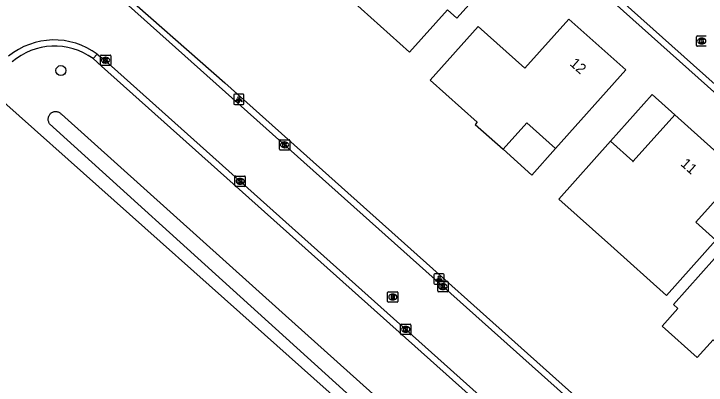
# Model space of a CAD drawing. Extents: x 157663 to 158496, y 379212 to 380934.
# Drawn here: x 158375.9 to 158443, y 380243 to 380278.9 of the extents above; entities that cross this region are included whole.
import ezdxf

# ---------------------------------------------------------------- set-up
doc = ezdxf.new("R2010")
doc.units = 0
for name, color, linetype in [('IMGEO_Boom', 7, 'Continuous'), ('IMGEO_Groenvoorziening', 7, 'Continuous'), ('IMGEO_Kolk', 7, 'Continuous'), ('IMGEO_Lichtpunt', 7, 'Continuous'), ('IMGEO_Pand', 7, 'Continuous'), ('IMGEO_Pand_nummerreeks', 7, 'Continuous'), ('IMGEO_Pand_overbouw', 7, 'Continuous'), ('IMGEO_Rijbaan_lokaal_open', 7, 'Continuous'), ('IMGEO_Rioolput', 7, 'Continuous'), ('IMGEO_Voetpad_open', 7, 'Continuous'), ('IMGEO_Waterloop', 7, 'Continuous')]:
    doc.layers.add(name, color=color, linetype=linetype)

msp = doc.modelspace()

# ---------------------------------------------------------------- linework, layer by layer
at = {"layer": 'IMGEO_Boom'}
msp.add_circle((158380.446, 380273.438), 0.489, dxfattribs=at)
at = {"layer": 'IMGEO_Groenvoorziening'}
msp.add_lwpolyline([(158436.002, 380187.68), (158429.436, 380221.799), (158397.765, 380250), (158373.398, 380271.696)], dxfattribs=at)
at = {"layer": 'IMGEO_Kolk'}
for p, q in [((158442.029, 380275.869), (158442.029, 380276.721)), ((158442.104, 380276.795), (158442.956, 380276.795)), ((158442.517, 380276.575), (158442.542, 380276.575)), ((158442.956, 380275.795), (158442.104, 380275.795)), ((158442.54, 380276.015), (158442.515, 380276.015)), ((158384.35, 380274.944), (158385.202, 380274.944)), ((158384.275, 380274.018), (158384.275, 380274.87)), ((158384.763, 380274.724), (158384.788, 380274.724)), ((158385.276, 380274.87), (158385.276, 380274.018)), ((158385.202, 380273.944), (158384.35, 380273.944)), ((158384.786, 380274.164), (158384.761, 380274.164)), ((158401.618, 380265.819), (158401.618, 380266.671)), ((158401.693, 380266.745), (158402.545, 380266.745)), ((158402.106, 380266.525), (158402.131, 380266.525)), ((158402.619, 380266.671), (158402.619, 380265.819)), ((158402.545, 380265.745), (158401.693, 380265.745)), ((158402.129, 380265.965), (158402.104, 380265.965)), ((158397.307, 380262.295), (158397.307, 380263.147)), ((158397.382, 380263.221), (158398.234, 380263.221)), ((158397.795, 380263.001), (158397.82, 380263.001)), ((158398.308, 380263.147), (158398.308, 380262.295)), ((158398.234, 380262.221), (158397.382, 380262.221)), ((158397.818, 380262.441), (158397.793, 380262.441)), ((158416.95, 380252.091), (158416.95, 380252.943)), ((158417.025, 380253.017), (158417.877, 380253.017)), ((158417.951, 380252.943), (158417.951, 380252.091)), ((158417.461, 380252.237), (158417.436, 380252.237)), ((158417.438, 380252.797), (158417.463, 380252.797)), ((158417.877, 380252.017), (158417.025, 380252.017)), ((158413.351, 380247.943), (158413.351, 380248.795)), ((158413.426, 380248.869), (158414.278, 380248.869)), ((158414.352, 380248.795), (158414.352, 380247.943)), ((158413.839, 380248.649), (158413.864, 380248.649)), ((158414.278, 380247.869), (158413.426, 380247.869)), ((158413.862, 380248.089), (158413.837, 380248.089))]:
    msp.add_line(p, q, dxfattribs=at)
for points in [[(158442.029, 380275.869), (158442.029, 380276.721)], [(158442.104, 380276.795), (158442.956, 380276.795)], [(158442.35, 380276.495), (158442.473, 380276.495), (158442.473, 380276.344), (158442.603, 380276.495), (158442.767, 380276.495), (158442.621, 380276.344), (158442.774, 380276.095), (158442.622, 380276.095), (158442.537, 380276.259), (158442.473, 380276.192), (158442.473, 380276.095), (158442.35, 380276.095), (158442.35, 380276.495)], [(158442.956, 380275.795), (158442.104, 380275.795)], [(158384.35, 380274.944), (158385.202, 380274.944)], [(158384.275, 380274.018), (158384.275, 380274.87)], [(158384.596, 380274.644), (158384.719, 380274.644), (158384.719, 380274.493), (158384.849, 380274.644), (158385.013, 380274.644), (158384.867, 380274.493), (158385.02, 380274.244), (158384.868, 380274.244), (158384.783, 380274.408), (158384.719, 380274.341), (158384.719, 380274.244), (158384.596, 380274.244), (158384.596, 380274.644)], [(158385.276, 380274.87), (158385.276, 380274.018)], [(158385.202, 380273.944), (158384.35, 380273.944)], [(158401.618, 380265.819), (158401.618, 380266.671)], [(158401.693, 380266.745), (158402.545, 380266.745)], [(158401.939, 380266.445), (158402.062, 380266.445), (158402.062, 380266.294), (158402.192, 380266.445), (158402.356, 380266.445), (158402.21, 380266.294), (158402.363, 380266.045), (158402.211, 380266.045), (158402.126, 380266.209), (158402.062, 380266.142), (158402.062, 380266.045), (158401.939, 380266.045), (158401.939, 380266.445)], [(158402.619, 380266.671), (158402.619, 380265.819)], [(158402.545, 380265.745), (158401.693, 380265.745)], [(158397.307, 380262.295), (158397.307, 380263.147)], [(158397.382, 380263.221), (158398.234, 380263.221)], [(158397.628, 380262.921), (158397.751, 380262.921), (158397.751, 380262.77), (158397.881, 380262.921), (158398.045, 380262.921), (158397.899, 380262.77), (158398.052, 380262.521), (158397.9, 380262.521), (158397.815, 380262.685), (158397.751, 380262.618), (158397.751, 380262.521), (158397.628, 380262.521), (158397.628, 380262.921)], [(158398.308, 380263.147), (158398.308, 380262.295)], [(158398.234, 380262.221), (158397.382, 380262.221)], [(158416.95, 380252.091), (158416.95, 380252.943)], [(158417.025, 380253.017), (158417.877, 380253.017)], [(158417.951, 380252.943), (158417.951, 380252.091)], [(158417.271, 380252.717), (158417.394, 380252.717), (158417.394, 380252.566), (158417.524, 380252.717), (158417.688, 380252.717), (158417.542, 380252.566), (158417.695, 380252.317), (158417.543, 380252.317), (158417.458, 380252.481), (158417.394, 380252.414), (158417.394, 380252.317), (158417.271, 380252.317), (158417.271, 380252.717)], [(158417.877, 380252.017), (158417.025, 380252.017)], [(158413.351, 380247.943), (158413.351, 380248.795)], [(158413.426, 380248.869), (158414.278, 380248.869)], [(158414.352, 380248.795), (158414.352, 380247.943)], [(158413.672, 380248.569), (158413.795, 380248.569), (158413.795, 380248.418), (158413.925, 380248.569), (158414.089, 380248.569), (158413.943, 380248.418), (158414.096, 380248.169), (158413.944, 380248.169), (158413.859, 380248.333), (158413.795, 380248.266), (158413.795, 380248.169), (158413.672, 380248.169), (158413.672, 380248.569)], [(158414.278, 380247.869), (158413.426, 380247.869)]]:
    msp.add_lwpolyline(points, dxfattribs=at)
for centre, start, end in [((158442.106, 380276.719), 91.55205, 178.44795), ((158442.106, 380276.719), 91.55205, 178.44795), ((158442.106, 380275.871), 181.55205, 268.44795), ((158442.106, 380275.871), 181.55205, 268.44795), ((158384.352, 380274.868), 91.55205, 178.44795), ((158384.352, 380274.868), 91.55205, 178.44795), ((158385.2, 380274.868), 1.55205, 88.44795), ((158385.2, 380274.868), 1.55205, 88.44795), ((158384.352, 380274.02), 181.55205, 268.44795), ((158384.352, 380274.02), 181.55205, 268.44795), ((158385.2, 380274.02), 271.55205, 358.44795), ((158385.2, 380274.02), 271.55205, 358.44795), ((158401.695, 380266.669), 91.55205, 178.44795), ((158401.695, 380266.669), 91.55205, 178.44795), ((158402.543, 380266.669), 1.55205, 88.44795), ((158402.543, 380266.669), 1.55205, 88.44795), ((158401.695, 380265.821), 181.55205, 268.44795), ((158401.695, 380265.821), 181.55205, 268.44795), ((158402.543, 380265.821), 271.55205, 358.44795), ((158402.543, 380265.821), 271.55205, 358.44795), ((158397.384, 380263.145), 91.55205, 178.44795), ((158397.384, 380263.145), 91.55205, 178.44795), ((158398.232, 380263.145), 1.55205, 88.44795), ((158398.232, 380263.145), 1.55205, 88.44795), ((158397.384, 380262.297), 181.55205, 268.44795), ((158397.384, 380262.297), 181.55205, 268.44795), ((158398.232, 380262.297), 271.55205, 358.44795), ((158398.232, 380262.297), 271.55205, 358.44795), ((158417.027, 380252.941), 91.55205, 178.44795), ((158417.027, 380252.941), 91.55205, 178.44795), ((158417.875, 380252.941), 1.55205, 88.44795), ((158417.875, 380252.941), 1.55205, 88.44795), ((158417.027, 380252.093), 181.55205, 268.44795), ((158417.027, 380252.093), 181.55205, 268.44795), ((158417.875, 380252.093), 271.55205, 358.44795), ((158417.875, 380252.093), 271.55205, 358.44795), ((158413.428, 380248.793), 91.55205, 178.44795), ((158413.428, 380248.793), 91.55205, 178.44795), ((158414.276, 380248.793), 1.55205, 88.44795), ((158414.276, 380248.793), 1.55205, 88.44795), ((158413.428, 380247.945), 181.55205, 268.44795), ((158413.428, 380247.945), 181.55205, 268.44795), ((158414.276, 380247.945), 271.55205, 358.44795), ((158414.276, 380247.945), 271.55205, 358.44795)]:
    msp.add_arc(centre, 0.0765, start, end, dxfattribs=at)
for centre, major_axis, ratio, start_param, end_param in [((158442.516, 380276.295), (-0.387, 0.002), 0.722429, 4.712389, 7.853982), ((158442.541, 380276.295), (-0.39, 0.002), 0.717154, 1.570796, 4.712389), ((158384.762, 380274.444), (-0.387, 0.002), 0.722429, 4.712389, 7.853982), ((158384.787, 380274.444), (-0.39, 0.002), 0.717154, 1.570796, 4.712389), ((158402.105, 380266.245), (-0.387, 0.002), 0.722429, 4.712389, 7.853982), ((158402.13, 380266.245), (-0.39, 0.002), 0.717154, 1.570796, 4.712389), ((158397.794, 380262.721), (-0.387, 0.002), 0.722429, 4.712389, 7.853982), ((158397.819, 380262.721), (-0.39, 0.002), 0.717154, 1.570796, 4.712389), ((158417.437, 380252.517), (-0.387, 0.002), 0.722429, 4.712389, 7.853982), ((158417.462, 380252.517), (-0.39, 0.002), 0.717154, 1.570796, 4.712389), ((158413.838, 380248.369), (-0.387, 0.002), 0.722429, 4.712389, 7.853982), ((158413.863, 380248.369), (-0.39, 0.002), 0.717154, 1.570796, 4.712389)]:
    msp.add_ellipse(centre, major_axis=major_axis, ratio=ratio, start_param=start_param, end_param=end_param, dxfattribs=at)
at = {"layer": 'IMGEO_Lichtpunt'}
for p, q in [((158397.184, 380271.042), (158397.184, 380270.235)), ((158397.184, 380271.042), (158397.184, 380270.235)), ((158398.086, 380271.137), (158397.278, 380271.137)), ((158398.086, 380271.137), (158397.278, 380271.137)), ((158398.18, 380270.235), (158398.18, 380271.042)), ((158398.18, 380270.235), (158398.18, 380271.042)), ((158397.278, 380270.141), (158398.086, 380270.141)), ((158397.278, 380270.141), (158398.086, 380270.141)), ((158416.588, 380253.647), (158416.588, 380252.84)), ((158416.588, 380253.647), (158416.588, 380252.84)), ((158417.49, 380253.742), (158416.682, 380253.742)), ((158417.49, 380253.742), (158416.682, 380253.742)), ((158417.584, 380252.84), (158417.584, 380253.647)), ((158417.584, 380252.84), (158417.584, 380253.647)), ((158416.682, 380252.746), (158417.49, 380252.746)), ((158416.682, 380252.746), (158417.49, 380252.746))]:
    msp.add_line(p, q, dxfattribs=at)
for points in [[(158397.558, 380270.706), (158397.597, 380270.678), (158397.409, 380270.416), (158397.371, 380270.443), (158397.558, 380270.706)], [(158397.66, 380270.658), (158397.707, 380270.658), (158397.707, 380270.336), (158397.66, 380270.336), (158397.66, 380270.658)], [(158397.77, 380270.678), (158397.808, 380270.705), (158397.995, 380270.443), (158397.956, 380270.415), (158397.77, 380270.678)], [(158416.962, 380253.311), (158417.001, 380253.283), (158416.813, 380253.021), (158416.775, 380253.048), (158416.962, 380253.311)], [(158417.064, 380253.263), (158417.111, 380253.263), (158417.111, 380252.941), (158417.064, 380252.941), (158417.064, 380253.263)], [(158417.174, 380253.283), (158417.212, 380253.31), (158417.399, 380253.048), (158417.36, 380253.02), (158417.174, 380253.283)]]:
    msp.add_lwpolyline(points, dxfattribs=at)
for centre in [(158397.683, 380270.84), (158417.087, 380253.445)]:
    msp.add_circle(centre, 0.0994, dxfattribs=at)
for centre, start, end in [((158397.278, 380271.042), 90, 180), ((158397.278, 380271.042), 90, 180), ((158398.086, 380271.042), 0, 90), ((158398.086, 380271.042), 0, 90), ((158397.278, 380270.235), 180, 270), ((158397.278, 380270.235), 180, 270), ((158398.086, 380270.235), 270, 0), ((158398.086, 380270.235), 270, 360), ((158416.682, 380253.647), 90, 180), ((158416.682, 380253.647), 90, 180), ((158417.49, 380253.647), 0, 90), ((158417.49, 380253.647), 0, 90), ((158416.682, 380252.84), 180, 270), ((158416.682, 380252.84), 180, 270), ((158417.49, 380252.84), 270, 0), ((158417.49, 380252.84), 270, 360)]:
    msp.add_arc(centre, 0.0946, start, end, dxfattribs=at)
at = {"layer": 'IMGEO_Pand'}
for points in [[(158422.031, 380282.141), (158418.975, 380284.874), (158419.836, 380285.836), (158412.917, 380292.022), (158408.761, 380287.374), (158410.312, 380285.987), (158406.707, 380281.954), (158414.228, 380275.23), (158417.897, 380279.333), (158418.799, 380278.526), (158422.031, 380282.141)], [(158435.167, 380273.507), (158429.659, 380278.431), (158425.402, 380273.668), (158420.872, 380277.718), (158416.219, 380272.513), (158420.786, 380268.431), (158420.591, 380268.213), (158423.278, 380265.812), (158425.568, 380268.374), (158425.57, 380268.376), (158425.573, 380268.377), (158425.576, 380268.377), (158425.579, 380268.376), (158425.582, 380268.374), (158428.359, 380265.892), (158435.167, 380273.507)], [(158439.909, 380269.158), (158435.877, 380264.648), (158435.874, 380264.646), (158435.871, 380264.645), (158435.867, 380264.646), (158435.863, 380264.648), (158433.686, 380266.594), (158428.685, 380260.999), (158433.714, 380256.503), (158439.126, 380251.665), (158443.899, 380257.009), (158441.96, 380258.741), (158446.225, 380263.512), (158439.909, 380269.158)], [(158450.556, 380258.336), (158447.331, 380254.728), (158445.082, 380256.738), (158439.782, 380250.791), (158440.224, 380250.396), (158438.683, 380248.673), (158442.08, 380245.635), (158443.62, 380247.358), (158444.259, 380246.787), (158448.438, 380243.05), (158453.561, 380248.779), (158454.653, 380250), (158456.98, 380252.603), (158455.593, 380253.843), (158455.942, 380254.234), (158455.099, 380254.988), (158454.745, 380254.591), (158450.556, 380258.336)]]:
    msp.add_lwpolyline(points, dxfattribs=at)
at = {"layer": 'IMGEO_Pand_overbouw'}
for points in [[(158439.909, 380269.158), (158437.725, 380271.111), (158433.686, 380266.594), (158435.863, 380264.648), (158435.867, 380264.646), (158435.871, 380264.645), (158435.874, 380264.646), (158435.877, 380264.648)], [(158423.278, 380265.812), (158426.062, 380263.323), (158428.359, 380265.892), (158425.582, 380268.374), (158425.579, 380268.376), (158425.576, 380268.377), (158425.573, 380268.377), (158425.57, 380268.376), (158425.568, 380268.374)]]:
    msp.add_lwpolyline(points, close=True, dxfattribs=at)
at = {"layer": 'IMGEO_Rijbaan_lokaal_open'}
for points in [[(158455.226, 380261.928), (158407.817, 380304.245)], [(158444.879, 380228.012), (158386.082, 380280.588)], [(158383.955, 380275.03), (158384.74, 380274.414), (158451.982, 380214.262)]]:
    msp.add_lwpolyline(points, dxfattribs=at)
msp.add_arc((158379.792, 380269.395), 7.006, 53.5431, 129.22981, dxfattribs=at)
at = {"layer": 'IMGEO_Rioolput'}
for p, q in [((158412.097, 380251.077), (158412.097, 380251.929)), ((158412.172, 380252.003), (158413.024, 380252.003)), ((158412.585, 380251.783), (158412.61, 380251.783)), ((158413.098, 380251.929), (158413.098, 380251.077)), ((158413.024, 380251.003), (158412.172, 380251.003)), ((158412.608, 380251.223), (158412.583, 380251.223))]:
    msp.add_line(p, q, dxfattribs=at)
for points in [[(158412.097, 380251.077), (158412.097, 380251.929)], [(158412.172, 380252.003), (158413.024, 380252.003)], [(158412.686, 380251.701), (158412.434, 380251.703), (158412.434, 380251.303)], [(158412.612, 380251.622), (158412.558, 380251.622), (158412.558, 380251.541)], [(158412.558, 380251.541), (158412.61, 380251.541)], [(158413.098, 380251.929), (158413.098, 380251.077)], [(158413.024, 380251.003), (158412.172, 380251.003)], [(158412.434, 380251.303), (158412.558, 380251.303), (158412.558, 380251.465), (158412.569, 380251.465)], [(158412.616, 380251.436), (158412.687, 380251.303), (158412.827, 380251.303), (158412.762, 380251.429)]]:
    msp.add_lwpolyline(points, dxfattribs=at)
for centre, radius, start, end in [((158412.174, 380251.927), 0.0765, 91.55205, 178.44795), ((158412.174, 380251.927), 0.0765, 91.55205, 178.44795), ((158412.594, 380251.73), 0.19, 274.7715, 282.96867), ((158412.618, 380251.526), 0.0964, 77.00612, 93.18647), ((158412.632, 380251.583), 0.0378, 276.66336, 79.67722), ((158412.685, 380251.591), 0.109, 350.36119, 89.41601), ((158412.683, 380251.591), 0.112, 277.58423, 350.98172), ((158412.667, 380251.376), 0.108, 29.51342, 73.79051), ((158413.022, 380251.927), 0.0765, 1.55205, 88.44795), ((158413.022, 380251.927), 0.0765, 1.55205, 88.44795), ((158412.174, 380251.079), 0.0765, 181.55205, 268.44795), ((158412.174, 380251.079), 0.0765, 181.55205, 268.44795), ((158412.568, 380251.412), 0.0533, 26.02933, 88.69889), ((158413.022, 380251.079), 0.0765, 271.55205, 358.44795), ((158413.022, 380251.079), 0.0765, 271.55205, 358.44795)]:
    msp.add_arc(centre, radius, start, end, dxfattribs=at)
for centre, major_axis, ratio, start_param, end_param in [((158412.584, 380251.503), (-0.387, 0.002), 0.722429, 4.712389, 7.853982), ((158412.609, 380251.503), (-0.39, 0.002), 0.717154, 1.570796, 4.712389)]:
    msp.add_ellipse(centre, major_axis=major_axis, ratio=ratio, start_param=start_param, end_param=end_param, dxfattribs=at)
at = {"layer": 'IMGEO_Voetpad_open'}
for points in [[(158407.523, 380303.702), (158454.843, 380261.446), (158454.886, 380261.5)], [(158385.44, 380281.833), (158396.328, 380272.254), (158441.82, 380231.568)], [(158383.955, 380275.03), (158383.552, 380274.605)], [(158383.552, 380274.605), (158384.385, 380273.86), (158433.567, 380229.917), (158440.634, 380223.603), (158439.348, 380222.215)]]:
    msp.add_lwpolyline(points, dxfattribs=at)
msp.add_arc((158379.838, 380269.534), 6.286, 53.78027, 131.09489, dxfattribs=at)
at = {"layer": 'IMGEO_Waterloop'}
msp.add_lwpolyline([(158427.682, 380224.496), (158399.532, 380250), (158379.344, 380268.291), (158379.319, 380268.331), (158379.286, 380268.393), (158379.259, 380268.458), (158379.238, 380268.524), (158379.223, 380268.593), (158379.214, 380268.662), (158379.212, 380268.733), (158379.215, 380268.803), (158379.225, 380268.872), (158379.241, 380268.94), (158379.264, 380269.007), (158379.291, 380269.071), (158379.325, 380269.133), (158379.368, 380269.196), (158379.41, 380269.245), (158379.456, 380269.29), (158379.505, 380269.33), (158379.558, 380269.366), (158379.615, 380269.397), (158379.673, 380269.423), (158379.734, 380269.443), (158379.796, 380269.458), (158379.859, 380269.467), (158379.923, 380269.471), (158379.987, 380269.469), (158380.051, 380269.461), (158380.113, 380269.448), (158380.175, 380269.429), (158380.234, 380269.404), (158380.291, 380269.375), (158380.345, 380269.34), (158380.395, 380269.301), (158380.442, 380269.258), (158380.485, 380269.21), (158401.892, 380250), (158428.835, 380225.823)], dxfattribs=at)

# ---------------------------------------------------------------- texts
at = {"layer": 'IMGEO_Pand_nummerreeks'}
for s, p in [('12', (158429.677, 380274.016)), ('11', (158440.415, 380264.308))]:
    msp.add_text(s, height=1, rotation=318.20273, dxfattribs=at).set_placement(p)

doc.saveas('drawing.dxf')
